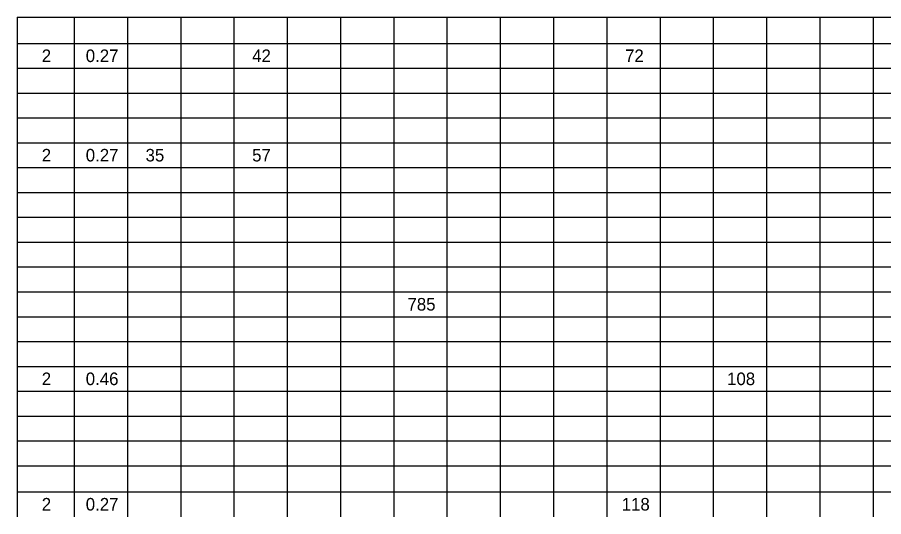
# Model space of a CAD drawing. Extents: x 0.2 to 34.2, y 0 to 22.
# Drawn here: x 14.91 to 24.55, y 4.96 to 10.52 of the extents above; entities that cross this region are included whole.
import ezdxf

# ---------------------------------------------------------------- set-up
doc = ezdxf.new("R2010")
doc.units = 0
doc.layers.add('SH_Text', color=7, linetype='Continuous')

msp = doc.modelspace()

# ---------------------------------------------------------------- linework, layer by layer
at = {"layer": 'SH_Text'}
for p, q in [((14.908, 10.5229), (15.5405, 10.5229)), ((14.908, 10.5229), (14.908, 10.233)), ((15.5405, 10.5229), (24.4346, 10.5229)), ((15.5405, 10.5229), (15.5405, 10.233)), ((16.1334, 10.5229), (16.1334, 10.233)), ((16.7264, 10.5229), (16.7264, 10.233)), ((17.3193, 10.5229), (17.3193, 10.233)), ((17.9122, 10.5229), (17.9122, 10.233)), ((18.5052, 10.5229), (18.5052, 10.233)), ((19.0981, 10.5229), (19.0981, 10.233)), ((19.6911, 10.5229), (19.6911, 10.233)), ((20.284, 10.5229), (20.284, 10.233)), ((20.8769, 10.5229), (20.8769, 10.233)), ((21.4699, 10.5229), (21.4699, 10.233)), ((22.0628, 10.5229), (22.0628, 10.233)), ((22.6558, 10.5229), (22.6558, 10.233)), ((23.2487, 10.5229), (23.2487, 10.233)), ((23.8417, 10.5229), (23.8417, 10.233)), ((24.4346, 10.5229), (32.1955, 10.5229)), ((24.4346, 10.5229), (24.4346, 10.233)), ((14.908, 10.233), (15.5405, 10.233)), ((14.908, 10.233), (14.908, 9.9563)), ((15.5405, 10.233), (24.4346, 10.233)), ((15.5405, 10.233), (15.5405, 9.9563)), ((16.1334, 10.233), (16.1334, 9.9563)), ((16.7264, 10.233), (16.7264, 9.9563)), ((17.3193, 10.233), (17.3193, 9.9563)), ((17.9122, 10.233), (17.9122, 9.9563)), ((18.5052, 10.233), (18.5052, 9.9563)), ((19.0981, 10.233), (19.0981, 9.9563)), ((19.6911, 10.233), (19.6911, 9.9563)), ((20.284, 10.233), (20.284, 9.9563)), ((20.8769, 10.233), (20.8769, 9.9563)), ((21.4699, 10.233), (21.4699, 9.9563)), ((22.0628, 10.233), (22.0628, 9.9563)), ((22.6558, 10.233), (22.6558, 9.9563)), ((23.2487, 10.233), (23.2487, 9.9563)), ((23.8417, 10.233), (23.8417, 9.9563)), ((24.4346, 10.233), (32.1955, 10.233)), ((24.4346, 10.233), (24.4346, 9.9563)), ((14.908, 9.9563), (15.5405, 9.9563)), ((14.908, 9.9563), (14.908, 9.6796)), ((15.5405, 9.9563), (24.4346, 9.9563)), ((15.5405, 9.9563), (15.5405, 9.6796)), ((16.1334, 9.9563), (16.1334, 9.6796)), ((16.7264, 9.9563), (16.7264, 9.6796)), ((17.3193, 9.9563), (17.3193, 9.6796)), ((17.9122, 9.9563), (17.9122, 9.6796)), ((18.5052, 9.9563), (18.5052, 9.6796)), ((19.0981, 9.9563), (19.0981, 9.6796)), ((19.6911, 9.9563), (19.6911, 9.6796)), ((20.284, 9.9563), (20.284, 9.6796)), ((20.8769, 9.9563), (20.8769, 9.6796)), ((21.4699, 9.9563), (21.4699, 9.6796)), ((22.0628, 9.9563), (22.0628, 9.6796)), ((22.6558, 9.9563), (22.6558, 9.6796)), ((23.2487, 9.9563), (23.2487, 9.6796)), ((23.8417, 9.9563), (23.8417, 9.6796)), ((24.4346, 9.9563), (32.1955, 9.9563)), ((24.4346, 9.9563), (24.4346, 9.6796)), ((14.908, 9.6796), (15.5405, 9.6796)), ((14.908, 9.6796), (14.908, 9.4029)), ((15.5405, 9.6796), (24.4346, 9.6796)), ((15.5405, 9.6796), (15.5405, 9.4029)), ((16.1334, 9.6796), (16.1334, 9.4029)), ((16.7264, 9.6796), (16.7264, 9.4029)), ((17.3193, 9.6796), (17.3193, 9.4029)), ((17.9122, 9.6796), (17.9122, 9.4029)), ((18.5052, 9.6796), (18.5052, 9.4029)), ((19.0981, 9.6796), (19.0981, 9.4029)), ((19.6911, 9.6796), (19.6911, 9.4029)), ((20.284, 9.6796), (20.284, 9.4029)), ((20.8769, 9.6796), (20.8769, 9.4029)), ((21.4699, 9.6796), (21.4699, 9.4029)), ((22.0628, 9.6796), (22.0628, 9.4029)), ((22.6558, 9.6796), (22.6558, 9.4029)), ((23.2487, 9.6796), (23.2487, 9.4029)), ((23.8417, 9.6796), (23.8417, 9.4029)), ((24.4346, 9.6796), (32.1955, 9.6796)), ((24.4346, 9.6796), (24.4346, 9.4029)), ((14.908, 9.4029), (15.5405, 9.4029)), ((14.908, 9.4029), (14.908, 9.1262)), ((15.5405, 9.4029), (24.4346, 9.4029)), ((15.5405, 9.4029), (15.5405, 9.1262)), ((16.1334, 9.4029), (16.1334, 9.1262)), ((16.7264, 9.4029), (16.7264, 9.1262)), ((17.3193, 9.4029), (17.3193, 9.1262)), ((17.9122, 9.4029), (17.9122, 9.1262)), ((18.5052, 9.4029), (18.5052, 9.1262)), ((19.0981, 9.4029), (19.0981, 9.1262)), ((19.6911, 9.4029), (19.6911, 9.1262)), ((20.284, 9.4029), (20.284, 9.1262)), ((20.8769, 9.4029), (20.8769, 9.1262)), ((21.4699, 9.4029), (21.4699, 9.1262)), ((22.0628, 9.4029), (22.0628, 9.1262)), ((22.6558, 9.4029), (22.6558, 9.1262)), ((23.2487, 9.4029), (23.2487, 9.1262)), ((23.8417, 9.4029), (23.8417, 9.1262)), ((24.4346, 9.4029), (32.1955, 9.4029)), ((24.4346, 9.4029), (24.4346, 9.1262)), ((14.908, 9.1262), (15.5405, 9.1262)), ((14.908, 9.1262), (14.908, 8.8495)), ((15.5405, 9.1262), (24.4346, 9.1262)), ((15.5405, 9.1262), (15.5405, 8.8495)), ((16.1334, 9.1262), (16.1334, 8.8495)), ((16.7264, 9.1262), (16.7264, 8.8495)), ((17.3193, 9.1262), (17.3193, 8.8495)), ((17.9122, 9.1262), (17.9122, 8.8495)), ((18.5052, 9.1262), (18.5052, 8.8495)), ((19.0981, 9.1262), (19.0981, 8.8495)), ((19.6911, 9.1262), (19.6911, 8.8495)), ((20.284, 9.1262), (20.284, 8.8495)), ((20.8769, 9.1262), (20.8769, 8.8495)), ((21.4699, 9.1262), (21.4699, 8.8495)), ((22.0628, 9.1262), (22.0628, 8.8495)), ((22.6558, 9.1262), (22.6558, 8.8495)), ((23.2487, 9.1262), (23.2487, 8.8495)), ((23.8417, 9.1262), (23.8417, 8.8495)), ((24.4346, 9.1262), (32.1955, 9.1262)), ((24.4346, 9.1262), (24.4346, 8.8495)), ((14.908, 8.8495), (15.5405, 8.8495)), ((14.908, 8.8495), (14.908, 8.5728)), ((15.5405, 8.8495), (24.4346, 8.8495)), ((15.5405, 8.8495), (15.5405, 8.5728)), ((16.1334, 8.8495), (16.1334, 8.5728)), ((16.7264, 8.8495), (16.7264, 8.5728)), ((17.3193, 8.8495), (17.3193, 8.5728)), ((17.9122, 8.8495), (17.9122, 8.5728)), ((18.5052, 8.8495), (18.5052, 8.5728)), ((19.0981, 8.8495), (19.0981, 8.5728)), ((19.6911, 8.8495), (19.6911, 8.5728)), ((20.284, 8.8495), (20.284, 8.5728)), ((20.8769, 8.8495), (20.8769, 8.5728)), ((21.4699, 8.8495), (21.4699, 8.5728)), ((22.0628, 8.8495), (22.0628, 8.5728)), ((22.6558, 8.8495), (22.6558, 8.5728)), ((23.2487, 8.8495), (23.2487, 8.5728)), ((23.8417, 8.8495), (23.8417, 8.5728)), ((24.4346, 8.8495), (32.1955, 8.8495)), ((24.4346, 8.8495), (24.4346, 8.5728)), ((14.908, 8.5728), (15.5405, 8.5728)), ((14.908, 8.5728), (14.908, 8.2961)), ((15.5405, 8.5728), (24.4346, 8.5728)), ((15.5405, 8.5728), (15.5405, 8.2961)), ((16.1334, 8.5728), (16.1334, 8.2961)), ((16.7264, 8.5728), (16.7264, 8.2961)), ((17.3193, 8.5728), (17.3193, 8.2961)), ((17.9122, 8.5728), (17.9122, 8.2961)), ((18.5052, 8.5728), (18.5052, 8.2961)), ((19.0981, 8.5728), (19.0981, 8.2961)), ((19.6911, 8.5728), (19.6911, 8.2961)), ((20.284, 8.5728), (20.284, 8.2961)), ((20.8769, 8.5728), (20.8769, 8.2961)), ((21.4699, 8.5728), (21.4699, 8.2961)), ((22.0628, 8.5728), (22.0628, 8.2961)), ((22.6558, 8.5728), (22.6558, 8.2961)), ((23.2487, 8.5728), (23.2487, 8.2961)), ((23.8417, 8.5728), (23.8417, 8.2961)), ((24.4346, 8.5728), (32.1955, 8.5728)), ((24.4346, 8.5728), (24.4346, 8.2961)), ((14.908, 8.2961), (15.5405, 8.2961)), ((14.908, 8.2961), (14.908, 8.0194)), ((15.5405, 8.2961), (24.4346, 8.2961)), ((15.5405, 8.2961), (15.5405, 8.0194)), ((16.1334, 8.2961), (16.1334, 8.0194)), ((16.7264, 8.2961), (16.7264, 8.0194)), ((17.3193, 8.2961), (17.3193, 8.0194)), ((17.9122, 8.2961), (17.9122, 8.0194)), ((18.5052, 8.2961), (18.5052, 8.0194)), ((19.0981, 8.2961), (19.0981, 8.0194)), ((19.6911, 8.2961), (19.6911, 8.0194)), ((20.284, 8.2961), (20.284, 8.0194)), ((20.8769, 8.2961), (20.8769, 8.0194)), ((21.4699, 8.2961), (21.4699, 8.0194)), ((22.0628, 8.2961), (22.0628, 8.0194)), ((22.6558, 8.2961), (22.6558, 8.0194)), ((23.2487, 8.2961), (23.2487, 8.0194)), ((23.8417, 8.2961), (23.8417, 8.0194)), ((24.4346, 8.2961), (32.1955, 8.2961)), ((24.4346, 8.2961), (24.4346, 8.0194)), ((14.908, 8.0194), (15.5405, 8.0194)), ((14.908, 8.0194), (14.908, 7.7427)), ((15.5405, 8.0194), (24.4346, 8.0194)), ((15.5405, 8.0194), (15.5405, 7.7427)), ((16.1334, 8.0194), (16.1334, 7.7427)), ((16.7264, 8.0194), (16.7264, 7.7427)), ((17.3193, 8.0194), (17.3193, 7.7427)), ((17.9122, 8.0194), (17.9122, 7.7427)), ((18.5052, 8.0194), (18.5052, 7.7427)), ((19.0981, 8.0194), (19.0981, 7.7427)), ((19.6911, 8.0194), (19.6911, 7.7427)), ((20.284, 8.0194), (20.284, 7.7427)), ((20.8769, 8.0194), (20.8769, 7.7427)), ((21.4699, 8.0194), (21.4699, 7.7427)), ((22.0628, 8.0194), (22.0628, 7.7427)), ((22.6558, 8.0194), (22.6558, 7.7427)), ((23.2487, 8.0194), (23.2487, 7.7427)), ((23.8417, 8.0194), (23.8417, 7.7427)), ((24.4346, 8.0194), (32.1955, 8.0194)), ((24.4346, 8.0194), (24.4346, 7.7427)), ((14.908, 7.7427), (15.5405, 7.7427)), ((14.908, 7.7427), (14.908, 7.466)), ((15.5405, 7.7427), (24.4346, 7.7427)), ((15.5405, 7.7427), (15.5405, 7.466)), ((16.1334, 7.7427), (16.1334, 7.466)), ((16.7264, 7.7427), (16.7264, 7.466)), ((17.3193, 7.7427), (17.3193, 7.466)), ((17.9122, 7.7427), (17.9122, 7.466)), ((18.5052, 7.7427), (18.5052, 7.466)), ((19.0981, 7.7427), (19.0981, 7.466)), ((19.6911, 7.7427), (19.6911, 7.466)), ((20.284, 7.7427), (20.284, 7.466)), ((20.8769, 7.7427), (20.8769, 7.466)), ((21.4699, 7.7427), (21.4699, 7.466)), ((22.0628, 7.7427), (22.0628, 7.466)), ((22.6558, 7.7427), (22.6558, 7.466)), ((23.2487, 7.7427), (23.2487, 7.466)), ((23.8417, 7.7427), (23.8417, 7.466)), ((24.4346, 7.7427), (32.1955, 7.7427)), ((24.4346, 7.7427), (24.4346, 7.466)), ((14.908, 7.466), (15.5405, 7.466)), ((14.908, 7.466), (14.908, 7.1893)), ((15.5405, 7.466), (24.4346, 7.466)), ((15.5405, 7.466), (15.5405, 7.1893)), ((16.1334, 7.466), (16.1334, 7.1893)), ((16.7264, 7.466), (16.7264, 7.1893)), ((17.3193, 7.466), (17.3193, 7.1893)), ((17.9122, 7.466), (17.9122, 7.1893)), ((18.5052, 7.466), (18.5052, 7.1893)), ((19.0981, 7.466), (19.0981, 7.1893)), ((19.6911, 7.466), (19.6911, 7.1893)), ((20.284, 7.466), (20.284, 7.1893)), ((20.8769, 7.466), (20.8769, 7.1893)), ((21.4699, 7.466), (21.4699, 7.1893)), ((22.0628, 7.466), (22.0628, 7.1893)), ((22.6558, 7.466), (22.6558, 7.1893)), ((23.2487, 7.466), (23.2487, 7.1893)), ((23.8417, 7.466), (23.8417, 7.1893)), ((24.4346, 7.466), (32.1955, 7.466)), ((24.4346, 7.466), (24.4346, 7.1893)), ((14.908, 7.1893), (15.5405, 7.1893)), ((14.908, 7.1893), (14.908, 6.9126)), ((15.5405, 7.1893), (24.4346, 7.1893)), ((15.5405, 7.1893), (15.5405, 6.9126)), ((16.1334, 7.1893), (16.1334, 6.9126)), ((16.7264, 7.1893), (16.7264, 6.9126)), ((17.3193, 7.1893), (17.3193, 6.9126)), ((17.9122, 7.1893), (17.9122, 6.9126)), ((18.5052, 7.1893), (18.5052, 6.9126)), ((19.0981, 7.1893), (19.0981, 6.9126)), ((19.6911, 7.1893), (19.6911, 6.9126)), ((20.284, 7.1893), (20.284, 6.9126)), ((20.8769, 7.1893), (20.8769, 6.9126)), ((21.4699, 7.1893), (21.4699, 6.9126)), ((22.0628, 7.1893), (22.0628, 6.9126)), ((22.6558, 7.1893), (22.6558, 6.9126)), ((23.2487, 7.1893), (23.2487, 6.9126)), ((23.8417, 7.1893), (23.8417, 6.9126)), ((24.4346, 7.1893), (32.1955, 7.1893)), ((24.4346, 7.1893), (24.4346, 6.9126)), ((14.908, 6.9126), (15.5405, 6.9126)), ((14.908, 6.9126), (14.908, 6.6359)), ((15.5405, 6.9126), (24.4346, 6.9126)), ((15.5405, 6.9126), (15.5405, 6.6359)), ((16.1334, 6.9126), (16.1334, 6.6359)), ((16.7264, 6.9126), (16.7264, 6.6359)), ((17.3193, 6.9126), (17.3193, 6.6359)), ((17.9122, 6.9126), (17.9122, 6.6359)), ((18.5052, 6.9126), (18.5052, 6.6359)), ((19.0981, 6.9126), (19.0981, 6.6359)), ((19.6911, 6.9126), (19.6911, 6.6359)), ((20.284, 6.9126), (20.284, 6.6359)), ((20.8769, 6.9126), (20.8769, 6.6359)), ((21.4699, 6.9126), (21.4699, 6.6359)), ((22.0628, 6.9126), (22.0628, 6.6359)), ((22.6558, 6.9126), (22.6558, 6.6359)), ((23.2487, 6.9126), (23.2487, 6.6359)), ((23.8417, 6.9126), (23.8417, 6.6359)), ((24.4346, 6.9126), (32.1955, 6.9126)), ((24.4346, 6.9126), (24.4346, 6.6359)), ((14.908, 6.6359), (15.5405, 6.6359)), ((14.908, 6.6359), (14.908, 6.3591)), ((15.5405, 6.6359), (24.4346, 6.6359)), ((15.5405, 6.6359), (15.5405, 6.3591)), ((16.1334, 6.6359), (16.1334, 6.3591)), ((16.7264, 6.6359), (16.7264, 6.3591)), ((17.3193, 6.6359), (17.3193, 6.3591)), ((17.9122, 6.6359), (17.9122, 6.3591)), ((18.5052, 6.6359), (18.5052, 6.3591)), ((19.0981, 6.6359), (19.0981, 6.3591)), ((19.6911, 6.6359), (19.6911, 6.3591)), ((20.284, 6.6359), (20.284, 6.3591)), ((20.8769, 6.6359), (20.8769, 6.3591)), ((21.4699, 6.6359), (21.4699, 6.3591)), ((22.0628, 6.6359), (22.0628, 6.3591)), ((22.6558, 6.6359), (22.6558, 6.3591)), ((23.2487, 6.6359), (23.2487, 6.3591)), ((23.8417, 6.6359), (23.8417, 6.3591)), ((24.4346, 6.6359), (32.1955, 6.6359)), ((24.4346, 6.6359), (24.4346, 6.3591)), ((14.908, 6.3591), (15.5405, 6.3591)), ((14.908, 6.3591), (14.908, 5.529)), ((15.5405, 6.3591), (24.4346, 6.3591)), ((15.5405, 6.3591), (15.5405, 5.529)), ((16.1334, 6.3591), (16.1334, 5.529)), ((16.7264, 6.3591), (16.7264, 5.529)), ((17.3193, 6.3591), (17.3193, 5.529)), ((17.9122, 6.3591), (17.9122, 5.529)), ((18.5052, 6.3591), (18.5052, 5.529)), ((19.0981, 6.3591), (19.0981, 5.529)), ((19.6911, 6.3591), (19.6911, 5.529)), ((20.284, 6.3591), (20.284, 5.529)), ((20.8769, 6.3591), (20.8769, 5.529)), ((21.4699, 6.3591), (21.4699, 5.529)), ((22.0628, 6.3591), (22.0628, 5.529)), ((22.6558, 6.3591), (22.6558, 5.529)), ((23.2487, 6.3591), (23.2487, 5.529)), ((23.8417, 6.3591), (23.8417, 5.529)), ((24.4346, 6.3591), (32.1955, 6.3591)), ((24.4346, 6.3591), (24.4346, 5.529)), ((14.908, 6.0824), (15.5405, 6.0824)), ((15.5405, 6.0824), (24.4346, 6.0824)), ((24.4346, 6.0824), (32.1955, 6.0824)), ((14.908, 5.8057), (15.5405, 5.8057)), ((15.5405, 5.8057), (24.4346, 5.8057)), ((24.4346, 5.8057), (32.1955, 5.8057)), ((14.908, 5.529), (15.5405, 5.529)), ((14.908, 5.529), (14.908, 4.9624)), ((15.5405, 5.529), (24.4346, 5.529)), ((15.5405, 5.529), (15.5405, 4.9624)), ((16.1334, 5.529), (16.1334, 4.9624)), ((16.7264, 5.529), (16.7264, 4.9624)), ((17.3193, 5.529), (17.3193, 4.9624)), ((17.9122, 5.529), (17.9122, 4.9624)), ((18.5052, 5.529), (18.5052, 4.9624)), ((19.0981, 5.529), (19.0981, 4.9624)), ((19.6911, 5.529), (19.6911, 4.9624)), ((20.284, 5.529), (20.284, 4.9624)), ((20.8769, 5.529), (20.8769, 4.9624)), ((21.4699, 5.529), (21.4699, 4.9624)), ((22.0628, 5.529), (22.0628, 4.9624)), ((22.6558, 5.529), (22.6558, 4.9624)), ((23.2487, 5.529), (23.2487, 4.9624)), ((23.8417, 5.529), (23.8417, 4.9624)), ((24.4346, 5.529), (32.1955, 5.529)), ((24.4346, 5.529), (24.4346, 4.9624)), ((14.908, 5.2391), (15.5405, 5.2391)), ((15.5405, 5.2391), (24.4346, 5.2391)), ((24.4346, 5.2391), (32.1955, 5.2391))]:
    msp.add_line(p, q, dxfattribs=at)

# ---------------------------------------------------------------- texts
for s, p in [('2', (15.18, 10.0247)), ('0.27', (15.6697, 10.0247)), ('42', (17.5226, 10.0247)), ('72', (21.6732, 10.0247)), ('2', (15.18, 8.9179)), ('0.27', (15.6697, 8.9179)), ('35', (16.3355, 8.9179)), ('57', (17.5219, 8.9179)), ('785', (19.2513, 7.2576)), ('2', (15.18, 6.4275)), ('0.46', (15.6697, 6.4275)), ('108', (22.8093, 6.4275)), ('2', (15.18, 5.0308)), ('0.27', (15.6697, 5.0308)), ('118', (21.6362, 5.0308))]:
    msp.add_text(s, height=0.14, dxfattribs=at).set_placement(p)

doc.saveas('drawing.dxf')
